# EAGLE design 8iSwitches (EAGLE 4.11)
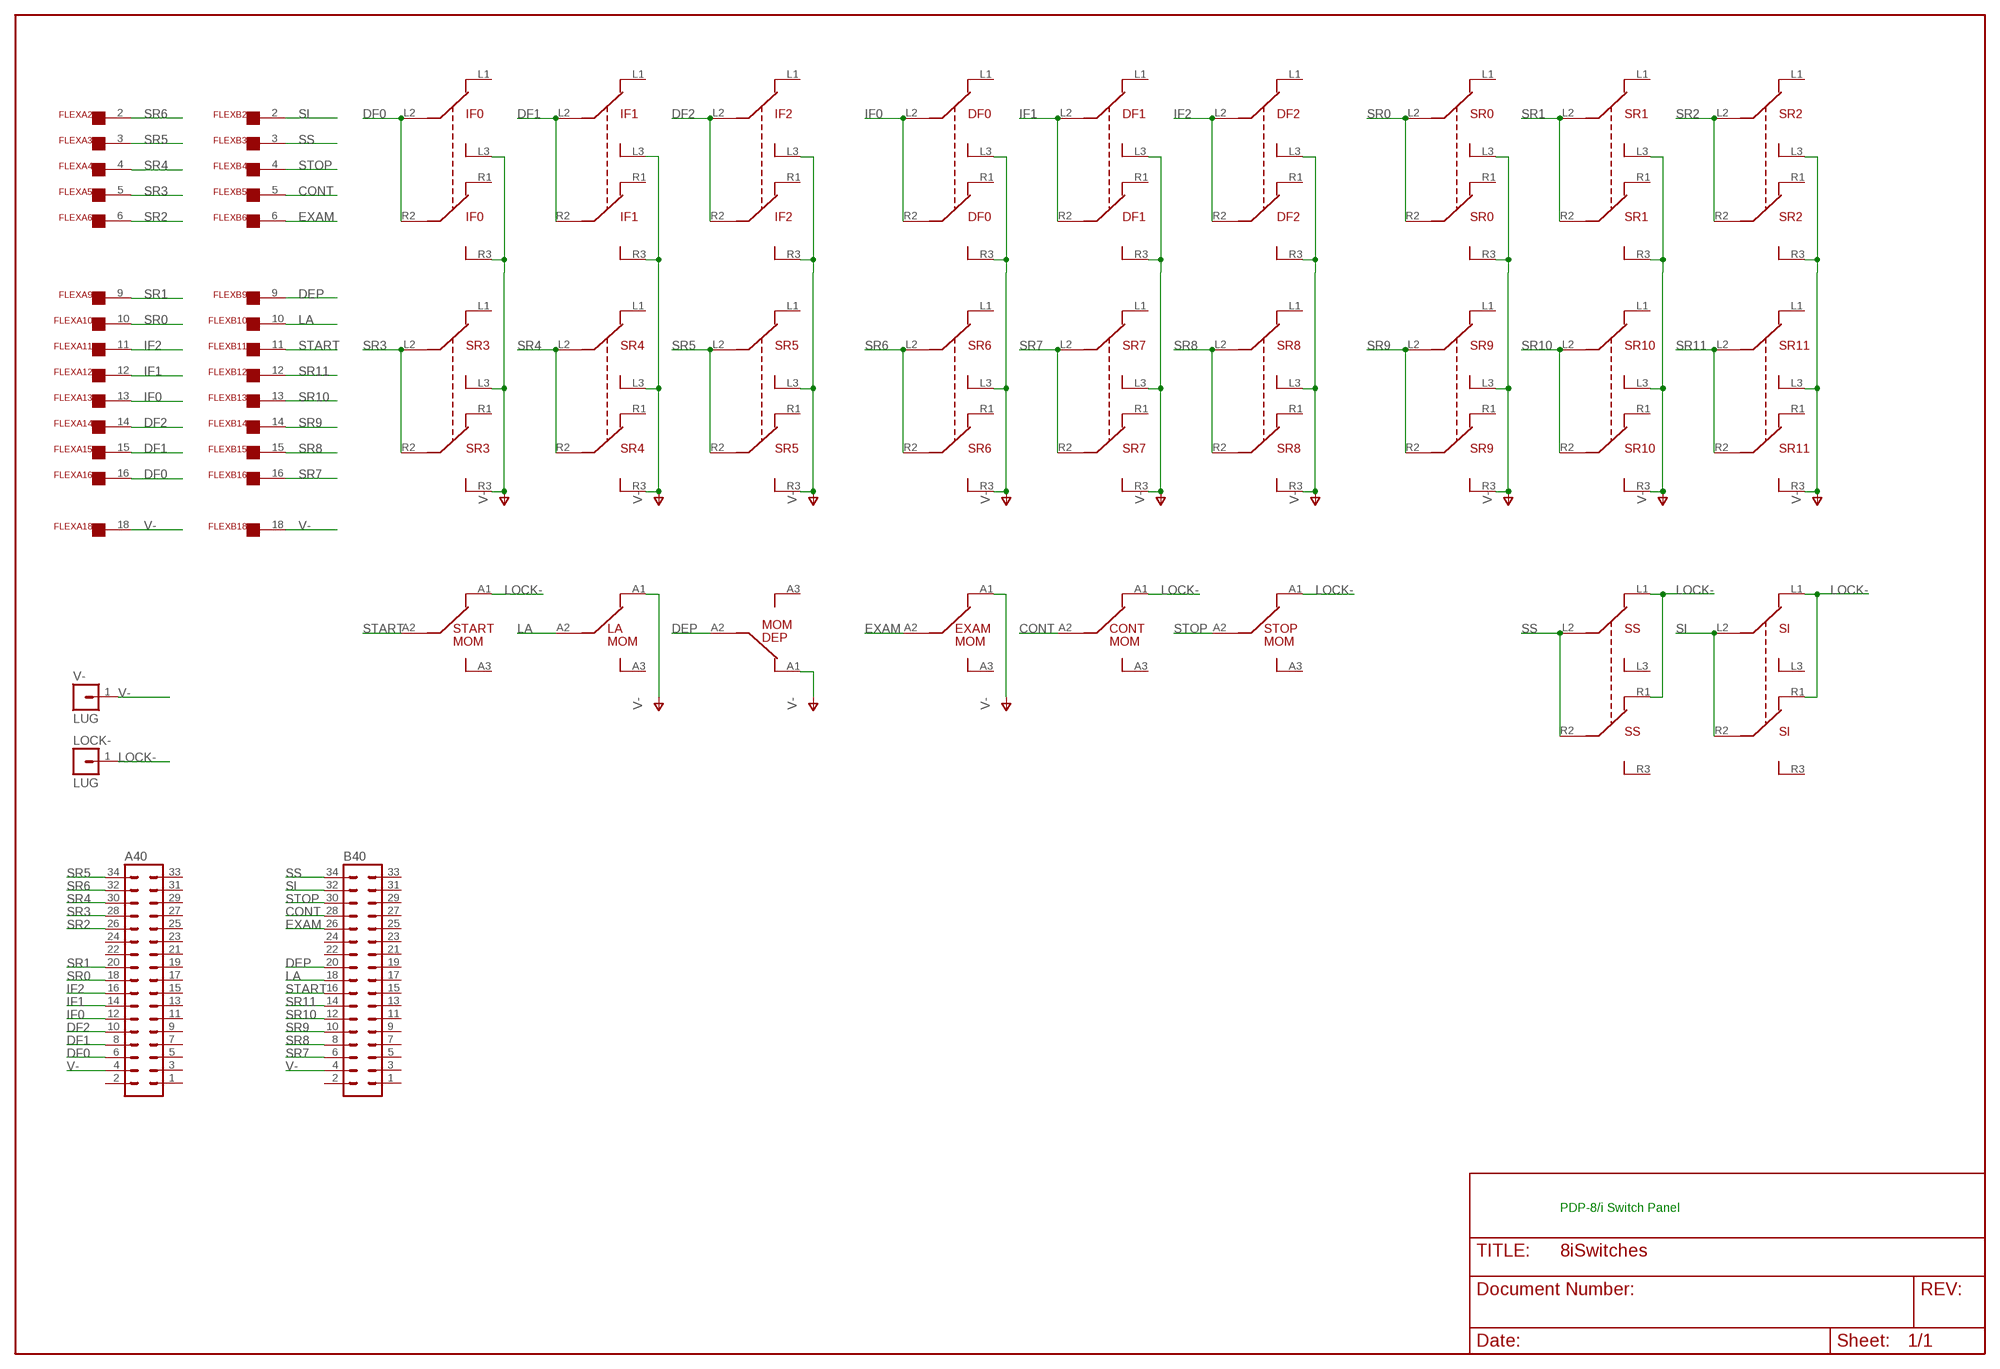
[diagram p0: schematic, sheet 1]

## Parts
A40  MA17-2  [MA17-2]
B40  MA17-2  [MA17-2]
CONT  SPDT8I  [SPDT8I]
DEP  SPDT8I  [SPDT8I]
DF0  DPDT8I  [DPDT8I]
DF1  DPDT8I  [DPDT8I]
DF2  DPDT8I  [DPDT8I]
EXAM  SPDT8I  [SPDT8I]
FLEXA  FLEX19  [FLEX19]
FLEXB  FLEX19  [FLEX19]
IF0  DPDT8I  [DPDT8I]
IF1  DPDT8I  [DPDT8I]
IF2  DPDT8I  [DPDT8I]
LA  SPDT8I  [SPDT8I]
LOCK-  LUG  [SPADELUG]
SI  DPDT8I  [DPDT8I]
SR0  DPDT8I  [DPDT8I]
SR1  DPDT8I  [DPDT8I]
SR2  DPDT8I  [DPDT8I]
SR3  DPDT8I  [DPDT8I]
SR4  DPDT8I  [DPDT8I]
SR5  DPDT8I  [DPDT8I]
SR6  DPDT8I  [DPDT8I]
SR7  DPDT8I  [DPDT8I]
SR8  DPDT8I  [DPDT8I]
SR9  DPDT8I  [DPDT8I]
SR10  DPDT8I  [DPDT8I]
SR11  DPDT8I  [DPDT8I]
SS  DPDT8I  [DPDT8I]
START  SPDT8I  [SPDT8I]
STOP  SPDT8I  [SPDT8I]
V-  LUG  [SPADELUG]

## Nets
CONT: B40.28 CONT.A2 FLEXB.5
DEP: B40.20 DEP.A2 FLEXB.9
DF0: A40.6 FLEXA.16 IF0.L2(A2) IF0.R2(B2)
DF1: A40.8 FLEXA.15 IF1.L2(A2) IF1.R2(B2)
DF2: A40.10 FLEXA.14 IF2.L2(A2) IF2.R2(B2)
EXAM: B40.26 EXAM.A2 FLEXB.6
IF0: A40.12 DF0.L2(A2) DF0.R2(B2) FLEXA.13
IF1: A40.14 DF1.L2(A2) DF1.R2(B2) FLEXA.12
IF2: A40.16 DF2.L2(A2) DF2.R2(B2) FLEXA.11
LA: B40.18 FLEXB.10 LA.A2
LOCK- [supply]: CONT.A1 LOCK-.1 SI.L1(A1) SI.R1(B1) SS.L1(A1) SS.R1(B1) START.A1 STOP.A1
SI: B40.32 FLEXB.2 SI.L2(A2) SI.R2(B2)
SR0: A40.18 FLEXA.10 SR0.L2(A2) SR0.R2(B2)
SR1: A40.20 FLEXA.9 SR1.L2(A2) SR1.R2(B2)
SR2: A40.26 FLEXA.6 SR2.L2(A2) SR2.R2(B2)
SR3: A40.28 FLEXA.5 SR3.L2(A2) SR3.R2(B2)
SR4: A40.30 FLEXA.4 SR4.L2(A2) SR4.R2(B2)
SR5: A40.34 FLEXA.3 SR5.L2(A2) SR5.R2(B2)
SR6: A40.32 FLEXA.2 SR6.L2(A2) SR6.R2(B2)
SR7: B40.6 FLEXB.16 SR7.L2(A2) SR7.R2(B2)
SR8: B40.8 FLEXB.15 SR8.L2(A2) SR8.R2(B2)
SR9: B40.10 FLEXB.14 SR9.L2(A2) SR9.R2(B2)
SR10: B40.12 FLEXB.13 SR10.L2(A2) SR10.R2(B2)
SR11: B40.14 FLEXB.12 SR11.L2(A2) SR11.R2(B2)
SS: B40.34 FLEXB.3 SS.L2(A2) SS.R2(B2)
START: B40.16 FLEXB.11 START.A2
STOP: B40.30 FLEXB.4 STOP.A2
V- [supply]: A40.4 B40.4 DEP.A1 DF0.L3(A3) DF0.R3(B3) DF1.L3(A3) DF1.R3(B3) DF2.L3(A3) DF2.R3(B3) EXAM.A1 FLEXA.18 FLEXB.18 IF0.L3(A3) IF0.R3(B3) IF1.L3(A3) IF1.R3(B3) IF2.L3(A3) IF2.R3(B3) LA.A1 SR0.L3(A3) SR0.R3(B3) SR1.L3(A3) SR1.R3(B3) SR2.L3(A3) SR2.R3(B3) SR3.L3(A3) SR3.R3(B3) SR4.L3(A3) SR4.R3(B3) SR5.L3(A3) SR5.R3(B3) SR6.L3(A3) SR6.R3(B3) SR7.L3(A3) SR7.R3(B3) SR8.L3(A3) SR8.R3(B3) SR9.L3(A3) SR9.R3(B3) SR10.L3(A3) SR10.R3(B3) SR11.L3(A3) SR11.R3(B3) V-.1
Unconnected: A40.1 A40.2 A40.3 A40.5 A40.7 A40.9 A40.11 A40.13 A40.15 A40.17 A40.19 A40.21 A40.22 A40.23 A40.24 A40.25 A40.27 A40.29 A40.31 A40.33 B40.1 B40.2 B40.3 B40.5 B40.7 B40.9 B40.11 B40.13 B40.15 B40.17 B40.19 B40.21 B40.22 B40.23 B40.24 B40.25 B40.27 B40.29 B40.31 B40.33 CONT.A3 DEP.A3 DF0.L1(A1) DF0.R1(B1) DF1.L1(A1) DF1.R1(B1) DF2.L1(A1) DF2.R1(B1) EXAM.A3 FLEXA.1 FLEXA.7 FLEXA.8 FLEXA.17 FLEXA.19 FLEXB.1 FLEXB.7 FLEXB.8 FLEXB.17 FLEXB.19 IF0.L1(A1) IF0.R1(B1) IF1.L1(A1) IF1.R1(B1) IF2.L1(A1) IF2.R1(B1) LA.A3 SI.L3(A3) SI.R3(B3) SR0.L1(A1) SR0.R1(B1) SR1.L1(A1) SR1.R1(B1) SR2.L1(A1) SR2.R1(B1) SR3.L1(A1) SR3.R1(B1) SR4.L1(A1) SR4.R1(B1) SR5.L1(A1) SR5.R1(B1) SR6.L1(A1) SR6.R1(B1) SR7.L1(A1) SR7.R1(B1) SR8.L1(A1) SR8.R1(B1) SR9.L1(A1) SR9.R1(B1) SR10.L1(A1) SR10.R1(B1) SR11.L1(A1) SR11.R1(B1) SS.L3(A3) SS.R3(B3) START.A3 STOP.A3

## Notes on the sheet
- PDP-8/i Switch Panel

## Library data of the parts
A40 B40 = con-lstb:MA17-2: PIN HEADER
CONT DEP EXAM LA START STOP = dec-con:SPDT8I: SPDT Momentary, as used in 8/i.
DF0 DF1 DF2 IF0 IF1 IF2 SI SR0 SR1-SR11 SS = dec-con:DPDT8I: DPDT switch as used in 8/i.
FLEXA FLEXB = dec-con:FLEX19
LOCK- V- = dec-con:LUG: Spade Lug

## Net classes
1 supply: width 0.762 mm

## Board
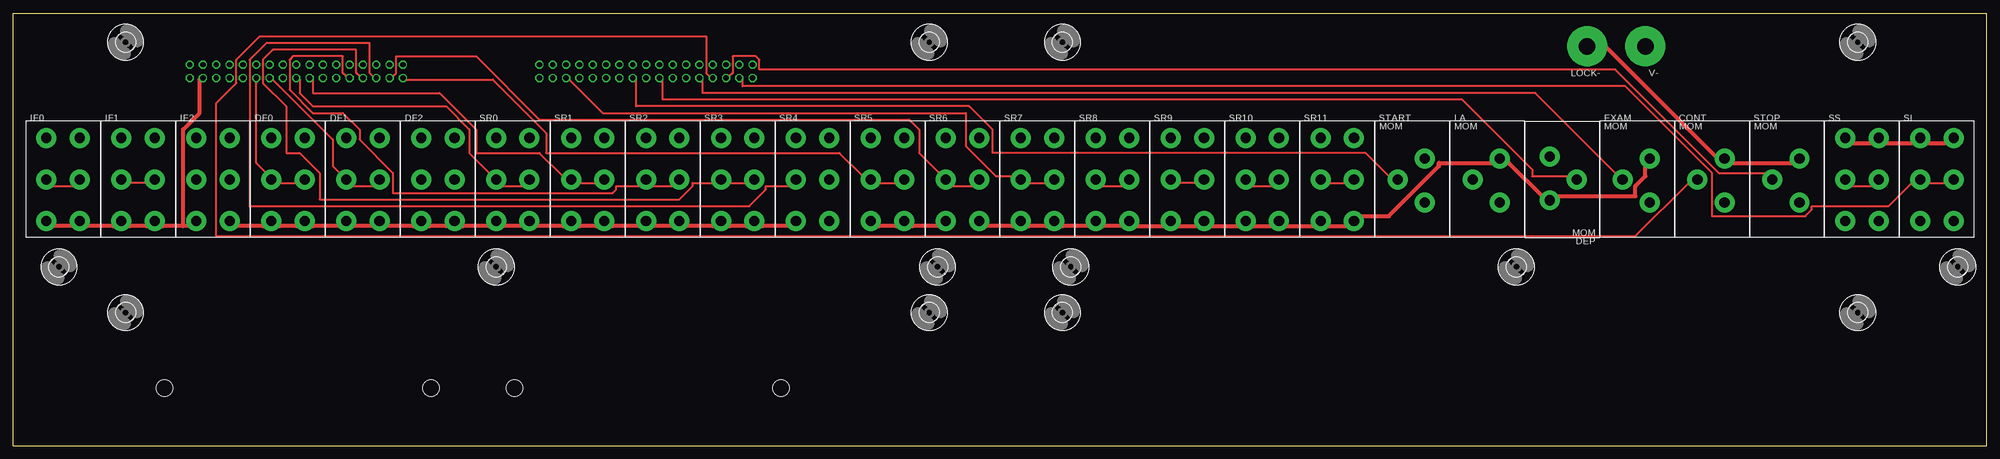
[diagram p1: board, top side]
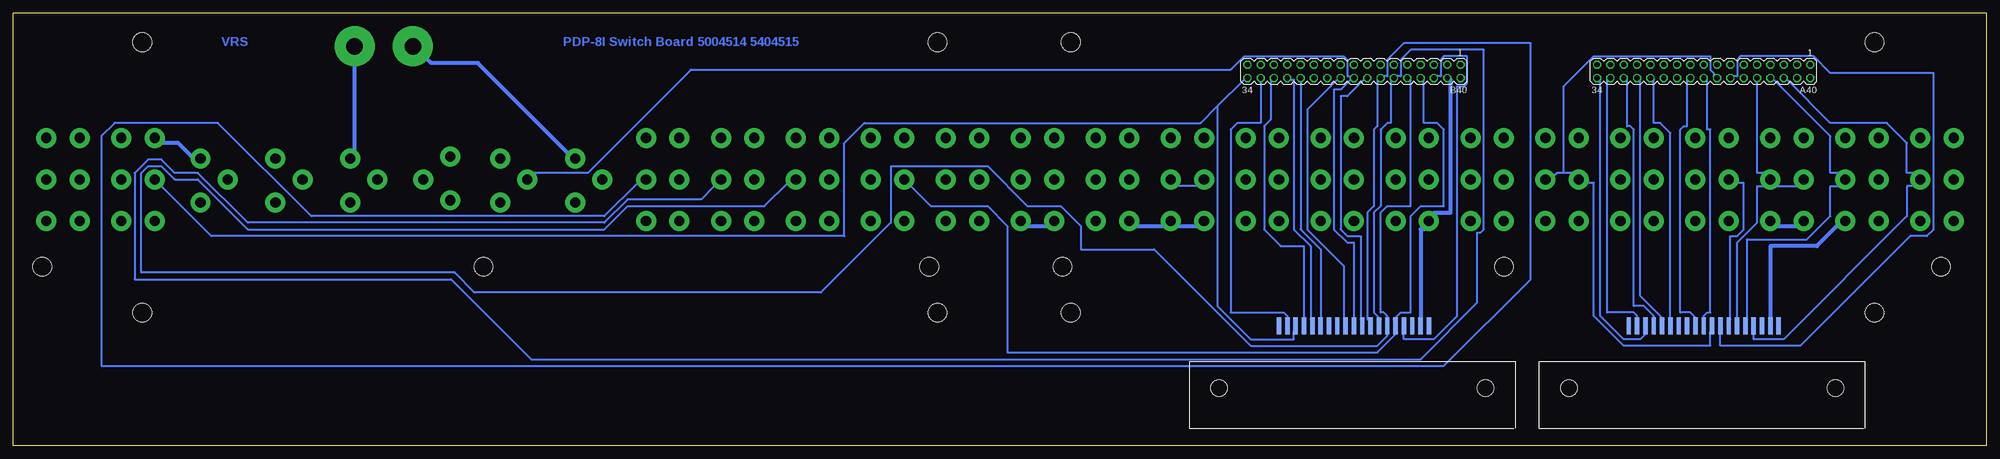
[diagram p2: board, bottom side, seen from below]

Size 376.24 x 82.55 mm. Coordinates in mm from the lower left corner, seen from the top.
Outline: 0,0 101.6,0 376.24,0 376.24,82.55 0,82.55 0,0
Copper layers (1*16): Top 0.035mm / dielectric 1.5mm / Bottom 0.035mm
Design rules "15mils": minimum track width 15mil, minimum drill 24mil, track to track 15mil, track to pad 10mil, pad to pad 10mil, via to via 10mil, smd to smd 10mil, copper to edge 25mil, drill to drill 10mil, minimum pad ring 10mil, minimum via ring 8mil, stop-mask expansion 0mil, vias tented up to drill 0mil, thermal gap 10mil

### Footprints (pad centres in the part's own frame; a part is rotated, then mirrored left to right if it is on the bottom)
MA17-2 = drill 1.016 octagon: 1 -20.32,-1.27; 2 -20.32,1.27; 3 -17.78,-1.27; 4 -17.78,1.27; 5 -15.24,-1.27; 6 -15.24,1.27; 7 -12.7,-1.27; 8 -12.7,1.27; 9 -10.16,-1.27; 10 -10.16,1.27; 11 -7.62,-1.27; 12 -7.62,1.27; 13 -5.08,-1.27; 14 -5.08,1.27; 15 -2.54,-1.27; 16 -2.54,1.27; 17 0,-1.27; 18 0,1.27; 19 2.54,-1.27; 20 2.54,1.27; 21 5.08,-1.27; 22 5.08,1.27; 23 7.62,-1.27; 24 7.62,1.27; 25 10.16,-1.27; 26 10.16,1.27; 27 12.7,-1.27; 28 12.7,1.27; 29 15.24,-1.27; 30 15.24,1.27; 31 17.78,-1.27; 32 17.78,1.27; 33 20.32,-1.27; 34 20.32,1.27
SPDT8I = drill 1.93 pad 3.81 round: A1 2.381,3.969; A2 -2.778,0; A3 2.381,-4.366
DPDT8I = drill 1.93 pad 3.81 round: L1 -3.175,7.938; L2 -3.175,0; L3 -3.175,-7.938; R1 3.175,7.938; R2 3.175,0; R3 3.175,-7.938
FLEX19 = smd 3.175 x 0.838: 1 0,14.287; 2 0,12.7; 3 0,11.113; 4 0,9.525; 5 0,7.938; 6 0,6.35; 7 0,4.763; 8 0,3.175; 9 0,1.587; 10 0,0; 11 0,-1.587; 12 0,-3.175; 13 0,-4.763; 14 0,-6.35; 15 0,-7.938; 16 0,-9.525; 17 0,-11.113; 18 0,-12.7; 19 0,-14.287
SPADELUG = drill 3.175 pad 7.62 round: 1 0,0
3,6 = hole 3.6: 0,0
STRAIN-RELIEF = hole 3.175: 7.62,56.515; 7.62,5.715

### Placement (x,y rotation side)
A40  53.98,71.44 180 bottom
B40  120.65,71.44 180 bottom
CONT  323.85,50.8 0 top
DEP  295.27,50.8 180 top
DF0  52.39,50.8 0 top
DF1  66.67,50.8 0 top
DF2  80.96,50.8 0 top
EXAM  309.56,50.8 0 top
FLEXA  53.98,22.86 90 bottom
FLEXB  120.65,22.86 90 bottom
IF0  9.53,50.8 0 top
IF1  23.81,50.8 0 top
IF2  38.1,50.8 0 top
LA  280.99,50.8 0 top
LOCK-  300.04,76.2 180 top
SI  366.71,50.8 0 top
SR0  95.25,50.8 0 top
SR1  109.54,50.8 0 top
SR2  123.83,50.8 0 top
SR3  138.11,50.8 0 top
SR4  152.4,50.8 0 top
SR5  166.69,50.8 0 top
SR6  180.97,50.8 0 top
SR7  195.26,50.8 0 top
SR8  209.55,50.8 0 top
SR9  223.84,50.8 0 top
SR10  238.12,50.8 0 top
SR11  252.41,50.8 0 top
SS  352.43,50.8 0 top
START  266.7,50.8 0 top
STOP  338.14,50.8 0 top
U$1  [3,6]  201.61,34.13 0 top
U$2  [3,6]  200.03,25.4 0 top
U$3  [3,6]  286.54,34.13 0 top
U$4  [3,6]  200.03,76.99 0 top
U$5  [3,6]  351.63,76.99 0 top
U$6  [3,6]  370.68,34.13 0 top
U$7  [3,6]  351.63,25.4 0 top
U$10  [3,6]  176.21,34.13 0 top
U$11  [3,6]  174.62,25.4 0 top
U$12  [3,6]  174.62,76.99 0 top
U$13  [3,6]  21.43,76.99 0 top
U$14  [3,6]  21.43,25.4 0 top
U$15  [3,6]  8.73,34.13 0 top
U$16  [3,6]  92.08,34.13 0 top
U$17  [STRAIN-RELIEF]  89.85,3.33 90 bottom
U$18  [STRAIN-RELIEF]  23.18,3.33 90 bottom
V-  311.15,76.2 180 top

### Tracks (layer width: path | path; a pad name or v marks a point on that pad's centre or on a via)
CONT
  Top 0.381: CONT.A2 319.4,50.16 309.25,40.01 38.73,40.01 38.73,65.41 42.55,69.22 42.55,73.66 46.99,78.11 132.08,78.11 132.08,71.12 132.72,70.48 B40.28
  Bottom 0.381: FLEXB.5 128.91,24.13 128.91,38.1 132.08,41.27 132.08,69.85 132.72,69.85 B40.28
DEP
  Top 0.381: DEP.A2 296.55,51.44 289.56,51.44 289.56,52.7 276.23,66.04 123.83,66.04 123.83,69.85 B40.20
  Bottom 0.381: B40.20 123.83,69.85 129.54,64.14 129.54,41.27 122.56,34.29 122.56,24.13 FLEXB.9
DF0
  Top 0.381: IF0.L2 7.62,49.53 11.43,49.53 IF0.R2
  Bottom 0.381: A40.6 38.1,69.85 29.84,61.59 19.05,61.59 15.24,57.78 15.24,52.07 13.97,52.07 IF0.R2 13.97,49.53 15.24,49.53 15.24,43.81 38.73,20.32 44.45,20.32 44.45,21.59 FLEXA.16
DF1
  Top 0.381: IF1.L2 22.23,50.16 25.4,50.16 IF1.R2
  Bottom 0.381: A40.8 40.64,69.85 29.84,59.05 29.84,52.07 27.94,52.07 IF1.R2 27.94,49.53 29.84,49.53 29.84,43.81 34.29,39.37 45.72,39.37 45.72,24.13 FLEXA.15
DF2
  Bottom 0.381: A40.10 43.81,69.85 43.81,52.07 42.55,52.07 IF2.R2 | FLEXA.14 47.62,24.13 47.62,38.73 43.81,42.55 43.81,49.53 42.55,49.53 IF2.R2 | IF2.L2 36.2,49.53 40.01,49.53 IF2.R2
EXAM
  Top 0.381: EXAM.A2 305.44,52.07 290.19,67.31 131.44,67.31 131.44,69.85 B40.26
  Bottom 0.381: FLEXB.6 127,24.13 127,37.47 130.81,41.27 130.81,69.85 B40.26
IF0
  Top 0.381: A40.12 46.35,69.85 46.35,53.98 48.26,52.07 DF0.L2 50.8,50.16 53.98,50.16 DF0.R2
  Bottom 0.381: FLEXA.13 48.9,24.13 48.9,40.01 47.62,40.01 46.35,41.27 46.35,50.16 47.62,50.16 DF0.L2
IF1
  Top 0.381: A40.14 49.53,69.85 60.96,58.42 60.96,53.34 62.23,52.07 DF1.L2 64.77,49.53 68.58,49.53 DF1.R2
  Bottom 0.381: FLEXA.12 50.8,21.59 50.8,19.05 35.56,19.05 14.61,40.01 11.43,40.01 10.16,41.27 10.16,71.12 29.84,71.12 33.02,74.3 46.99,74.3 47.62,73.66 47.62,70.48 48.26,70.48 A40.14
IF2
  Bottom 0.381: 80.64,52.07 80.64,68.58 74.93,74.3 52.7,74.3 52.7,71.75 52.07,71.12 52.07,70.48 A40.16 | 80.64,52.07 78.74,52.07 DF2.L2 76.2,50.16 74.93,50.16 74.93,24.77 69.22,19.05 52.7,19.05 52.7,21.59 FLEXA.11 | 80.64,52.07 81.92,52.07 82.55,51.44 DF2.R2
LA
  Bottom 0.381: FLEXB.10 120.65,24.13 120.65,38.73 121.92,38.73 124.46,41.27 124.46,67.94 123.19,67.94 121.28,69.85 B40.18 121.28,70.48 121.92,70.48 121.92,73.66 122.56,74.3 141.6,74.3 144.15,71.75 247.01,71.75 266.7,52.07 276.86,52.07 LA.A2
LOCK-
  Top 0.762: STOP.A1 339.09,53.98 327.66,53.98 CONT.A1 324.49,55.24 303.53,76.2 LOCK-.1 | SS.L1 350.52,57.78 354.33,57.78 SS.R1 356.87,57.78 361.95,57.78 SI.L1 365.12,57.78 368.3,57.78 SI.R1
  Bottom 0.762: STOP.A1 342.26,55.24 344.81,57.78 347.98,57.78 SS.L1 | START.A1 270.51,55.88 287.65,73.03 296.55,73.03 LOCK-.1
SI
  Top 0.381: SI.R2 368.3,50.16 365.12,50.16 SI.L2 361.95,50.16 357.5,45.72 342.9,45.72 342.9,45.09 341.63,43.81 323.85,43.81 323.85,52.07 307.34,68.58 139.06,68.58 139.06,69.85 B40.32
  Bottom 0.381: B40.32 138.43,69.85 138.43,61.59 142.88,61.59 144.15,60.33 144.15,25.4 133.99,25.4 133.35,24.77 133.35,24.13 FLEXB.2
SR0
  Top 0.381: SR0.R2 97.16,49.53 93.34,49.53 SR0.L2 90.81,52.07 87,55.88 87,60.33 82.55,64.77 57.15,64.77 54.61,67.31 54.61,69.85 A40.18
  Bottom 0.381: A40.18 53.34,69.85 53.34,60.33 52.7,60.33 52.7,25.4 53.34,25.4 53.98,24.77 53.98,24.13 FLEXA.10
SR1
  Top 0.381: SR1.R2 111.12,50.16 107.95,50.16 SR1.L2 104.78,51.44 100.33,55.88 88.27,55.88 88.27,60.33 81.28,67.31 57.15,67.31 57.15,69.85 A40.20
  Bottom 0.381: A40.20 57.15,69.85 57.15,60.96 57.78,60.96 58.42,60.33 58.42,25.4 56.52,25.4 55.24,24.13 FLEXA.9
SR2
  Top 0.381: SR2.R2 125.73,49.53 121.92,49.53 SR2.L2 119.38,49.53 114.94,49.53 114.94,48.9 114.3,48.26 72.39,48.26 72.39,52.07 66.04,58.42 66.04,60.33 62.87,63.5 57.15,63.5 52.7,67.94 52.7,73.66 53.34,74.3 62.87,74.3 62.87,71.12 63.5,70.48 A40.26
  Bottom 0.381: A40.26 63.5,69.85 63.5,61.59 62.23,61.59 60.33,59.69 60.33,24.13 FLEXA.6
SR3
  Top 0.381: SR3.R2 139.7,50.16 136.53,50.16 SR3.L2 133.35,50.16 129.54,50.16 129.54,49.53 127,46.99 58.42,46.99 58.42,52.07 54.61,55.88 52.07,55.88 52.07,64.77 47.62,69.22 47.62,73.66 49.53,75.56 65.41,75.56 65.41,71.12 66.04,70.48 A40.28
  Bottom 0.381: A40.28 66.04,69.85 66.04,28.57 61.59,24.13 FLEXA.5
SR4
  Top 0.381: SR4.L2 147.96,49.53 143.51,49.53 143.51,48.9 140.34,45.72 45.09,45.72 45.09,73.66 48.26,76.83 67.94,76.83 67.94,71.12 68.58,70.48 A40.30
  Bottom 0.381: SR4.L2 150.5,49.53 154.31,49.53 SR4.R2 | A40.30 68.58,69.85 68.58,60.96 67.94,60.96 67.31,60.33 67.31,26.67 65.41,26.67 63.5,24.77 63.5,24.13 FLEXA.4
SR5
  Top 0.381: SR5.R2 168.28,50.16 165.1,50.16 SR5.L2 161.93,51.44 157.48,55.88 101.6,55.88 101.6,59.69 91.44,69.85 74.93,69.85 A40.34
  Bottom 0.381: A40.34 73.66,69.85 73.66,24.77 69.22,20.32 66.04,20.32 64.77,21.59 FLEXA.3
SR6
  Top 0.381: SR6.R2 182.88,49.53 179.07,49.53 SR6.L2 176.53,52.07 172.72,55.88 172.72,60.33 170.81,62.23 100.33,62.23 88.27,74.3 73.03,74.3 73.03,71.12 72.39,70.48 A40.32
  Bottom 0.381: A40.32 72.39,69.85 72.39,25.4 67.31,25.4 66.67,24.77 66.67,24.13 FLEXA.2
SR7
  Top 0.381: SR7.R2 196.85,50.16 193.68,50.16 SR7.L2 190.5,51.44 187.32,51.44 181.61,57.15 181.61,63.5 112.39,63.5 106.05,69.85 B40.6
  Bottom 0.381: FLEXB.16 111.12,21.59 111.12,20.32 105.41,20.32 100.97,24.77 100.97,68.58 99.69,68.58 99.06,69.22 99.06,74.3 103.5,74.3 104.14,73.66 104.14,70.48 104.78,70.48 B40.6
SR8
  Top 0.381: SR8.L2 207.65,49.53 211.46,49.53 SR8.R2
  Bottom 0.381: B40.8 107.31,69.85 107.31,61.59 104.78,61.59 103.5,60.33 103.5,45.72 107.95,45.72 109.86,43.81 109.86,25.4 111.76,25.4 113.03,24.13 FLEXB.15 112.39,21.59 116.2,17.78 186.69,17.78 186.69,41.91 190.5,45.72 201.29,45.72 205.1,49.53 SR8.L2
SR9
  Top 0.381: SR9.L2 222.25,50.16 225.43,50.16 SR9.R2
  Bottom 0.381: B40.10 109.86,69.85 109.86,45.72 114.3,45.72 115.57,44.45 115.57,25.4 114.94,25.4 114.3,24.77 114.3,24.13 FLEXB.14 114.3,21.59 114.3,20.95 116.2,19.05 140.34,19.05 158.75,37.47 172.72,37.47 172.72,41.91 176.53,45.72 182.88,45.72 190.5,53.34 208.91,53.34 208.91,42.55 222.25,29.21 288.29,29.21 292.1,33.02 351.79,33.02 351.79,52.07 350.52,53.34 347.98,53.34 345.44,50.8 341,50.8 331.47,41.27 263.52,41.27 259.08,45.72 233.04,45.72 228.6,50.16 SR9.R2
SR10
  Top 0.381: SR10.L2 236.22,49.53 240.03,49.53 SR10.R2
  Bottom 0.381: FLEXB.13 115.57,24.13 116.84,25.4 116.84,44.45 115.57,45.72 115.57,60.33 114.3,61.59 113.67,61.59 113.67,69.85 B40.12 112.39,70.48 111.76,70.48 111.76,73.66 109.86,75.56 95.89,75.56 95.89,41.27 96.52,40.64 97.16,40.64 97.16,27.3 107.95,16.51 277.5,16.51 292.74,31.75 353.06,31.75 353.06,52.07 350.52,54.61 347.98,54.61 345.44,52.07 341,52.07 331.47,42.55 263.52,42.55 259.08,46.99 245.11,46.99 242.57,49.53 SR10.R2
SR11
  Top 0.381: SR11.L2 250.82,50.16 254,50.16 SR11.R2
  Bottom 0.381: FLEXB.12 117.47,24.13 118.11,24.13 118.11,44.45 116.84,45.72 116.84,60.33 116.2,60.96 116.2,69.85 B40.14 114.94,70.48 114.3,70.48 114.3,73.66 111.12,76.83 87,76.83 87,31.75 103.5,15.24 359.41,15.24 359.41,59.05 356.87,61.59 337.19,61.59 319.4,43.81 263.52,43.81 257.18,50.16 SR11.R2
SS
  Top 0.381: SS.R2 354.33,49.53 350.52,49.53 SS.L2
  Bottom 0.381: 146.69,64.77 149.86,61.59 214,61.59 217.81,57.78 217.81,40.01 338.45,40.01 347.98,49.53 SS.L2 | 146.69,64.77 141.6,69.85 B40.34 | 146.69,64.77 146.69,26.67 140.34,20.32 132.08,20.32 132.08,21.59 FLEXB.3
START
  Top 0.381: START.A2 262.25,51.44 257.81,55.88 186.69,55.88 186.69,60.33 182.25,64.77 118.75,64.77 118.75,69.85 B40.16
  Bottom 0.381: FLEXB.11 119.38,24.13 119.38,40.01 121.92,40.01 123.19,41.27 123.19,66.67 121.92,66.67 118.75,69.85 B40.16
STOP
  Top 0.381: STOP.A2 334.01,52.07 325.12,52.07 305.44,71.75 142.24,71.75 142.24,73.66 141.6,74.3 137.16,74.3 137.16,71.12 136.53,70.48 B40.30
  Bottom 0.381: FLEXB.4 130.18,24.13 130.18,38.1 134.62,38.1 137.79,41.27 137.79,60.96 136.53,62.23 136.53,69.85 B40.30
V-
  Top 0.762: EXAM.A1 311.15,53.34 311.15,51.44 309.25,49.53 309.25,47.62 294.64,47.62 DEP.A1 291.46,47.62 285.12,53.98 LA.A1 281.94,53.98 271.78,53.98 271.78,53.34 262.25,43.81 257.18,43.81 SR11.R3 254,41.91 250.82,41.91 SR11.L3 247.65,41.91 242.57,41.91 SR10.R3 240.03,41.91 236.22,41.91 SR10.L3 233.68,41.91 228.6,41.91 SR9.R3 225.43,41.91 222.25,41.91 SR9.L3 219.07,41.91 214,41.91 SR8.R3 211.46,41.91 207.65,41.91 SR8.L3 205.1,41.91 200.03,41.91 SR7.R3 196.85,41.91 193.68,41.91 SR7.L3 190.5,41.91 185.42,41.91 SR6.R3 | IF0.L3 7.62,41.91 11.43,41.91 IF0.R3 13.97,41.91 19.05,41.91 IF1.L3 22.23,41.91 25.4,41.91 IF1.R3 28.57,41.91 32.38,41.91 | IF2.R3 42.55,41.91 47.62,41.91 DF0.L3 50.8,41.91 53.98,41.91 DF0.R3 57.15,41.91 62.23,41.91 DF1.L3 64.77,41.91 68.58,41.91 DF1.R3 71.12,41.91 76.2,41.91 DF2.L3 79.38,41.91 82.55,41.91 DF2.R3 85.72,41.91 90.81,41.91 SR0.L3 93.34,41.91 97.16,41.91 SR0.R3 99.69,41.91 104.78,41.91 SR1.L3 107.95,41.91 111.12,41.91 SR1.R3 114.3,41.91 119.38,41.91 SR2.L3 121.92,41.91 125.73,41.91 SR2.R3 128.27,41.91 133.35,41.91 SR3.L3 136.53,41.91 139.7,41.91 SR3.R3 142.88,41.91 147.96,41.91 SR4.L3 | SR5.L3 165.1,41.91 168.28,41.91 SR5.R3 171.45,41.91 176.53,41.91 SR6.L3 | 32.38,41.91 33.66,41.91 IF2.L3 | 32.38,41.91 32.38,60.33 35.56,63.5 35.56,69.85 A40.4
  Bottom 0.762: SR6.L3 179.07,41.91 182.88,41.91 SR6.R3 | SR4.L3 150.5,41.91 154.31,41.91 SR4.R3 156.84,41.91 161.93,41.91 SR5.L3 | IF2.R3 40.01,41.91 36.2,41.91 IF2.L3 | FLEXA.18 41.27,24.13 41.27,38.1 32.38,38.1 28.57,41.91 IF1.R3 | V-.1 311.15,73.03 311.15,56.52 EXAM.A1 | FLEXB.18 107.95,24.13 107.95,41.27 107.31,41.27 SR1.L3 105.41,44.45 102.23,44.45 102.23,69.85 B40.4

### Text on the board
Bottom: PDP-8I Switch Board 5004514 5404515 | VRS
